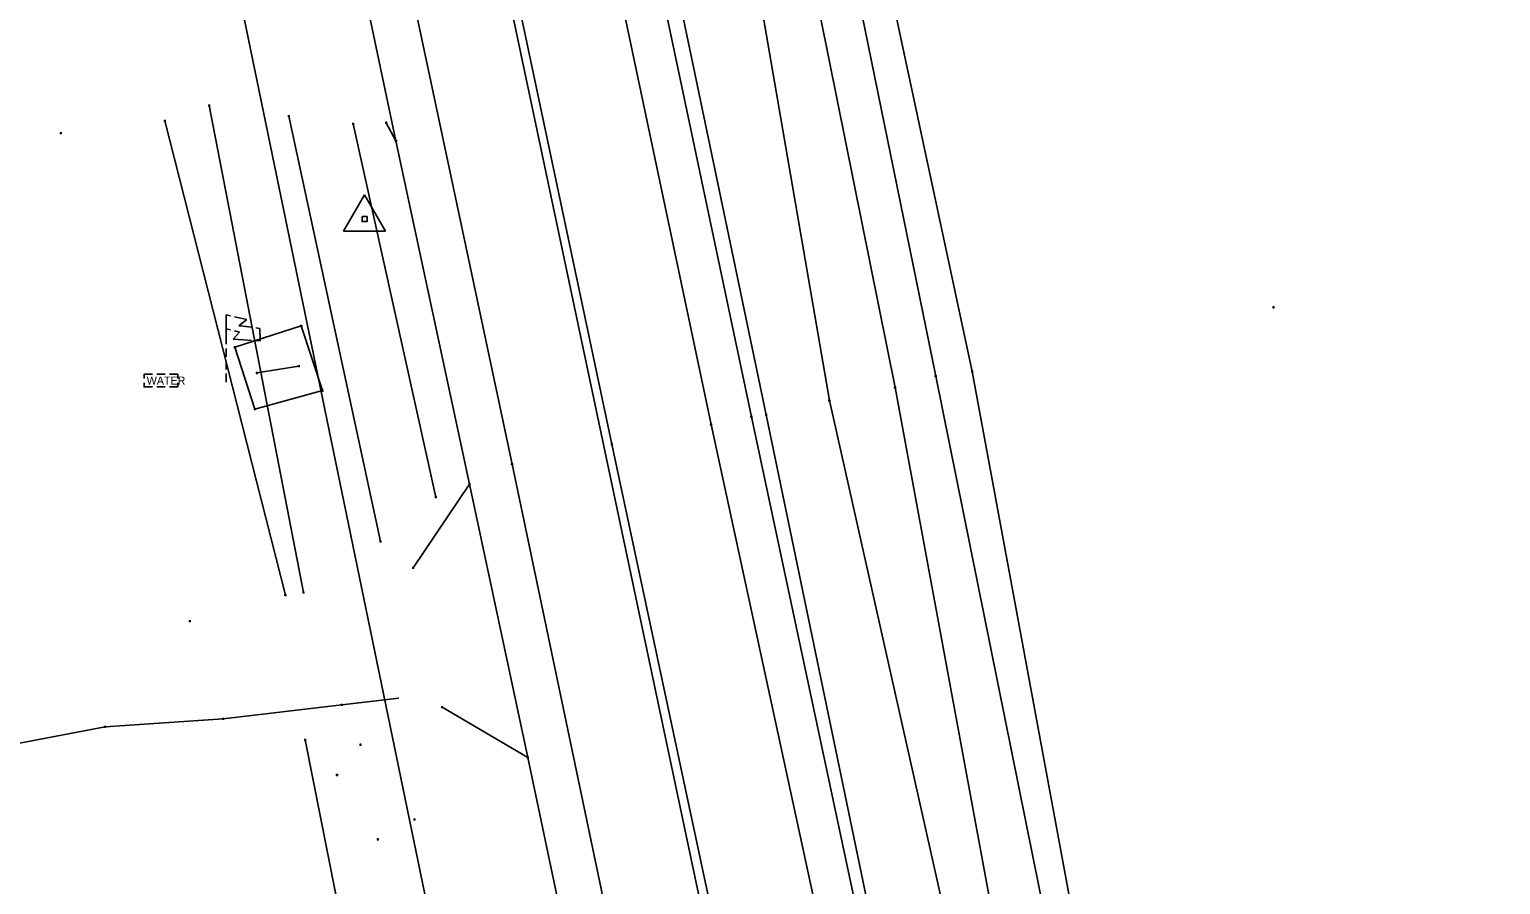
# Model space of a CAD drawing. Extents: x 1954856 to 2011933, y 399149 to 426294.
# Drawn here: x 2005094 to 2005268.6, y 407143.8 to 407245.4 of the extents above; entities that cross this region are included whole.
import ezdxf

# ---------------------------------------------------------------- set-up
doc = ezdxf.new("R2010")
doc.units = 0
for name, color, linetype in [('BankMent_ep', 7, 'Continuous'), ('BaselineSurvey', 7, 'Continuous'), ('Driveway_ep', 7, 'Continuous'), ('ElecAer_ep', 7, 'Continuous'), ('FlagPole_ep', 7, 'Continuous'), ('MeterWater_ep', 7, 'Continuous'), ('MonumentNL_ep', 7, 'Continuous'), ('PavtAsphalt_ep', 7, 'Continuous'), ('PavtAsphaltCrown_ep', 7, 'Continuous'), ('PointLocator_ep', 7, 'Continuous'), ('ShldrPaved_ep', 7, 'Continuous'), ('SignMulti_ep', 7, 'Continuous'), ('Stairs_ep', 7, 'Continuous'), ('TreeLineScatter_ep', 7, 'Continuous'), ('TreeLineWoods_ep', 7, 'Continuous')]:
    doc.layers.add(name, color=color, linetype=linetype)

msp = doc.modelspace()

# ---------------------------------------------------------------- linework, layer by layer
at = {"layer": 'BankMent_ep'}
for p, q in [((2005188.94, 407201.28), (2005172.13, 407299.28)), ((2005181.44, 407199.58), (2005161.06, 407297.29)), ((2005210.69, 407104.54), (2005188.94, 407201.28)), ((2005201.66, 407102.26), (2005181.44, 407199.58))]:
    msp.add_line(p, q, dxfattribs=at)
for points in [[(2005309.48, 406680.52), (2005302.97, 406714.33), (2005282.4, 406812.5), (2005263.07, 406909.67), (2005243.71, 407009.06), (2005221.27, 407106.71), (2005201.57, 407204.18), (2005181.73, 407301.56), (2005166.33, 407354.92)], [(2005306.06, 406678.23), (2005296.37, 406713.29), (2005277.07, 406810.93), (2005257.22, 406908.7), (2005233.22, 407007.14), (2005214.71, 407105.45), (2005196.74, 407202.84), (2005177.09, 407300.49), (2005163.81, 407354.47)], [(2005126.52, 407178.47), (2005115.31, 407236.34)], [(2005124.79, 407235.09), (2005135.67, 407184.52)], [(2005142.24, 407189.81), (2005132.4, 407234.16)]]:
    msp.add_lwpolyline(points, dxfattribs=at)
at = {"layer": 'BaselineSurvey'}
msp.add_line((2006223.92, 402174.38), (2005094.48, 407516.05), dxfattribs=at)
msp.add_line((2006223.92, 402174.38), (2005094.48, 407516.05), dxfattribs=at)
at = {"layer": 'Driveway_ep'}
for p, q in [((2005137.49, 407232.14), (2005136.34, 407234.3)), ((2005139.53, 407181.42), (2005146.22, 407191.34)), ((2005131.07, 407165.14), (2005116.97, 407163.47)), ((2005137.85, 407165.94), (2005131.07, 407165.14)), ((2005153.13, 407158.87), (2005142.98, 407164.86)), ((2005116.97, 407163.47), (2005102.98, 407162.51)), ((2005102.98, 407162.51), (2005083.54, 407158.8))]:
    msp.add_line(p, q, dxfattribs=at)
at = {"layer": 'ElecAer_ep'}
msp.add_lwpolyline([(2005261.7, 406565.27), (2005211.77, 406805.22), (2005164.45, 407028.42), (2005110.12, 407292.01), (2005075.05, 407240.4), (2005033.12, 407175.89)], dxfattribs=at)
at = {"layer": 'FlagPole_ep'}
for p, q in [((2005117.34, 407211.48), (2005117.84, 407211.36)), ((2005117.34, 407209.82), (2005117.34, 407211.48)), ((2005117.34, 407207.98), (2005117.34, 407209.82)), ((2005117.84, 407209.69), (2005117.34, 407209.82)), ((2005118.34, 407211.24), (2005119.79, 407210.91)), ((2005119.79, 407210.91), (2005118.83, 407210.17)), ((2005118.83, 407210.17), (2005119.34, 407210.11)), ((2005119.34, 407210.11), (2005120.34, 407209.99)), ((2005120.84, 407209.92), (2005121.34, 407209.86)), ((2005121.34, 407209.86), (2005121.37, 407208.37)), ((2005118.17, 407208.56), (2005118.92, 407209.41)), ((2005119.34, 407208.49), (2005118.17, 407208.56)), ((2005118.92, 407209.41), (2005118.34, 407209.56)), ((2005120.34, 407208.43), (2005119.34, 407208.49)), ((2005121.37, 407208.37), (2005120.84, 407208.4)), ((2005117.34, 407206.48), (2005117.34, 407207.48)), ((2005117.34, 407204.98), (2005117.34, 407205.98)), ((2005117.34, 407203.48), (2005117.34, 407204.48)), ((2005117.34, 407203.48), (2005117.34, 407203.48))]:
    msp.add_line(p, q, dxfattribs=at)
at = {"layer": 'MeterWater_ep'}
msp.add_line((2005109.59, 407203.65), (2005109.59, 407203.65), dxfattribs=at)
for points in [[(2005107.59, 407203.9), (2005107.59, 407204.4), (2005108.59, 407204.4)], [(2005108.59, 407202.9), (2005107.59, 407202.9), (2005107.59, 407203.4)], [(2005109.09, 407204.4), (2005110.09, 407204.4)], [(2005110.09, 407202.9), (2005109.09, 407202.9)], [(2005110.59, 407204.4), (2005111.59, 407204.4), (2005111.59, 407203.9)], [(2005111.59, 407203.4), (2005111.59, 407202.9), (2005110.59, 407202.9)]]:
    msp.add_lwpolyline(points, dxfattribs=at)
at = {"layer": 'MonumentNL_ep'}
for p, q in [((2005131.26, 407221.4), (2005133.76, 407225.73)), ((2005133.76, 407225.73), (2005136.26, 407221.4)), ((2005133.76, 407222.84), (2005133.76, 407222.84)), ((2005131.26, 407221.4), (2005136.26, 407221.4))]:
    msp.add_line(p, q, dxfattribs=at)
msp.add_lwpolyline([(2005133.46, 407223.14), (2005134.06, 407223.14), (2005134.06, 407222.54), (2005133.46, 407222.54)], close=True, dxfattribs=at)
at = {"layer": 'PavtAsphalt_ep'}
for p, q in [((2005174.9, 407198.44), (2005154.4, 407295.58)), ((2005151.27, 407193.74), (2005130.48, 407291.72)), ((2005195.99, 407101.08), (2005174.9, 407198.44)), ((2005171.88, 407095.33), (2005151.27, 407193.74))]:
    msp.add_line(p, q, dxfattribs=at)
at = {"layer": 'PavtAsphaltCrown_ep'}
for p, q in [((2005163.1, 407196.11), (2005142.45, 407294.03)), ((2005183.98, 407098.33), (2005163.1, 407196.11))]:
    msp.add_line(p, q, dxfattribs=at)
at = {"layer": 'PointLocator_ep'}
for p, q in [((2005115.44, 407236.34), (2005115.19, 407236.34)), ((2005115.31, 407236.22), (2005115.31, 407236.47)), ((2005115.31, 407236.34), (2005115.31, 407236.34)), ((2005110.18, 407234.52), (2005109.93, 407234.52)), ((2005110.06, 407234.4), (2005110.06, 407234.65)), ((2005110.06, 407234.52), (2005110.06, 407234.52)), ((2005124.91, 407235.09), (2005124.66, 407235.09)), ((2005124.79, 407234.96), (2005124.79, 407235.21)), ((2005124.79, 407235.09), (2005124.79, 407235.09)), ((2005132.4, 407234.04), (2005132.4, 407234.29)), ((2005136.46, 407234.3), (2005136.21, 407234.3)), ((2005136.34, 407234.18), (2005136.34, 407234.43)), ((2005136.34, 407234.3), (2005136.34, 407234.3)), ((2005097.82, 407233.06), (2005097.57, 407233.06)), ((2005097.69, 407232.93), (2005097.69, 407233.18)), ((2005097.69, 407233.06), (2005097.69, 407233.06)), ((2005132.53, 407234.16), (2005132.28, 407234.16)), ((2005132.4, 407234.16), (2005132.4, 407234.16)), ((2005137.62, 407232.14), (2005137.37, 407232.14)), ((2005137.49, 407232.01), (2005137.49, 407232.26)), ((2005137.49, 407232.14), (2005137.49, 407232.14)), ((2005241.8, 407212.36), (2005241.55, 407212.36)), ((2005241.68, 407212.23), (2005241.68, 407212.48)), ((2005241.68, 407212.36), (2005241.68, 407212.36)), ((2005126.38, 407210.16), (2005126.13, 407210.16)), ((2005126.25, 407210.03), (2005126.25, 407210.28)), ((2005126.25, 407210.16), (2005126.25, 407210.16)), ((2005118.5, 407207.61), (2005118.25, 407207.61)), ((2005118.37, 407207.49), (2005118.37, 407207.74)), ((2005118.37, 407207.61), (2005118.37, 407207.61)), ((2005121.09, 407204.56), (2005120.84, 407204.56)), ((2005120.96, 407204.43), (2005120.96, 407204.68)), ((2005120.96, 407204.56), (2005120.96, 407204.56)), ((2005126.07, 407205.37), (2005125.82, 407205.37)), ((2005125.95, 407205.25), (2005125.95, 407205.5)), ((2005125.95, 407205.37), (2005125.95, 407205.37)), ((2005206.02, 407204.74), (2005205.77, 407204.74)), ((2005205.9, 407204.61), (2005205.9, 407204.86)), ((2005205.9, 407204.74), (2005205.9, 407204.74)), ((2005196.86, 407202.84), (2005196.61, 407202.84)), ((2005196.74, 407202.71), (2005196.74, 407202.96)), ((2005196.74, 407202.84), (2005196.74, 407202.84)), ((2005201.69, 407204.18), (2005201.44, 407204.18)), ((2005201.57, 407204.06), (2005201.57, 407204.31)), ((2005201.57, 407204.18), (2005201.57, 407204.18)), ((2005128.88, 407202.46), (2005128.63, 407202.46)), ((2005128.76, 407202.33), (2005128.76, 407202.58)), ((2005128.76, 407202.46), (2005128.76, 407202.46)), ((2005189.06, 407201.28), (2005188.81, 407201.28)), ((2005188.94, 407201.15), (2005188.94, 407201.4)), ((2005188.94, 407201.28), (2005188.94, 407201.28)), ((2005120.87, 407200.26), (2005120.62, 407200.26)), ((2005120.74, 407200.14), (2005120.74, 407200.39)), ((2005120.74, 407200.26), (2005120.74, 407200.26)), ((2005179.81, 407199.37), (2005179.56, 407199.37)), ((2005179.68, 407199.25), (2005179.68, 407199.5)), ((2005179.68, 407199.37), (2005179.68, 407199.37)), ((2005181.57, 407199.58), (2005181.32, 407199.58)), ((2005181.44, 407199.45), (2005181.44, 407199.7)), ((2005181.44, 407199.58), (2005181.44, 407199.58)), ((2005175.02, 407198.44), (2005174.77, 407198.44)), ((2005174.9, 407198.31), (2005174.9, 407198.56)), ((2005174.9, 407198.44), (2005174.9, 407198.44)), ((2005163.23, 407196.11), (2005162.98, 407196.11)), ((2005163.1, 407195.99), (2005163.1, 407196.24)), ((2005163.1, 407196.11), (2005163.1, 407196.11)), ((2005151.39, 407193.74), (2005151.14, 407193.74)), ((2005151.27, 407193.61), (2005151.27, 407193.86)), ((2005151.27, 407193.74), (2005151.27, 407193.74)), ((2005146.35, 407191.34), (2005146.1, 407191.34)), ((2005146.22, 407191.22), (2005146.22, 407191.47)), ((2005146.22, 407191.34), (2005146.22, 407191.34)), ((2005142.36, 407189.81), (2005142.11, 407189.81)), ((2005142.24, 407189.69), (2005142.24, 407189.94)), ((2005142.24, 407189.81), (2005142.24, 407189.81)), ((2005135.79, 407184.52), (2005135.54, 407184.52)), ((2005135.67, 407184.4), (2005135.67, 407184.65)), ((2005135.67, 407184.52), (2005135.67, 407184.52)), ((2005139.66, 407181.42), (2005139.41, 407181.42)), ((2005139.53, 407181.29), (2005139.53, 407181.54)), ((2005139.53, 407181.42), (2005139.53, 407181.42)), ((2005124.36, 407178.06), (2005124.36, 407178.31)), ((2005126.64, 407178.47), (2005126.39, 407178.47)), ((2005126.52, 407178.35), (2005126.52, 407178.6)), ((2005126.52, 407178.47), (2005126.52, 407178.47)), ((2005124.48, 407178.18), (2005124.23, 407178.18)), ((2005124.36, 407178.18), (2005124.36, 407178.18)), ((2005113.15, 407175.07), (2005112.9, 407175.07)), ((2005113.03, 407174.94), (2005113.03, 407175.19)), ((2005113.03, 407175.07), (2005113.03, 407175.07)), ((2005131.2, 407165.14), (2005130.95, 407165.14)), ((2005131.07, 407165.02), (2005131.07, 407165.27)), ((2005131.07, 407165.14), (2005131.07, 407165.14)), ((2005143.1, 407164.86), (2005142.85, 407164.86)), ((2005142.98, 407164.74), (2005142.98, 407164.99)), ((2005142.98, 407164.86), (2005142.98, 407164.86)), ((2005102.98, 407162.39), (2005102.98, 407162.64)), ((2005117.09, 407163.47), (2005116.84, 407163.47)), ((2005116.97, 407163.34), (2005116.97, 407163.59)), ((2005116.97, 407163.47), (2005116.97, 407163.47)), ((2005103.1, 407162.51), (2005102.85, 407162.51)), ((2005102.98, 407162.51), (2005102.98, 407162.51)), ((2005126.84, 407160.96), (2005126.59, 407160.96)), ((2005126.72, 407160.83), (2005126.72, 407161.08)), ((2005126.72, 407160.96), (2005126.72, 407160.96)), ((2005133.41, 407160.4), (2005133.16, 407160.4)), ((2005133.29, 407160.27), (2005133.29, 407160.52)), ((2005133.29, 407160.4), (2005133.29, 407160.4)), ((2005153.26, 407158.87), (2005153.01, 407158.87)), ((2005153.13, 407158.74), (2005153.13, 407158.99)), ((2005153.13, 407158.87), (2005153.13, 407158.87)), ((2005130.62, 407156.8), (2005130.37, 407156.8)), ((2005130.49, 407156.67), (2005130.49, 407156.92)), ((2005130.49, 407156.8), (2005130.49, 407156.8)), ((2005139.81, 407151.52), (2005139.56, 407151.52)), ((2005139.69, 407151.39), (2005139.69, 407151.64)), ((2005139.69, 407151.52), (2005139.69, 407151.52)), ((2005135.45, 407149.15), (2005135.2, 407149.15)), ((2005135.33, 407149.03), (2005135.33, 407149.28)), ((2005135.33, 407149.15), (2005135.33, 407149.15))]:
    msp.add_line(p, q, dxfattribs=at)
at = {"layer": 'ShldrPaved_ep'}
for p, q in [((2005179.68, 407199.37), (2005159.17, 407296.71)), ((2005137.49, 407232.14), (2005130.38, 407265.93)), ((2005146.22, 407191.34), (2005137.49, 407232.14)), ((2005200.41, 407102.08), (2005179.68, 407199.37)), ((2005153.13, 407158.87), (2005146.22, 407191.34)), ((2005166.79, 407094.24), (2005153.13, 407158.87))]:
    msp.add_line(p, q, dxfattribs=at)
at = {"layer": 'SignMulti_ep'}
msp.add_lwpolyline([(2005120.96, 407204.56), (2005125.95, 407205.37)], dxfattribs=at)
at = {"layer": 'Stairs_ep'}
msp.add_lwpolyline([(2005128.76, 407202.46), (2005120.74, 407200.26), (2005118.37, 407207.61), (2005126.25, 407210.16)], close=True, dxfattribs=at)
at = {"layer": 'TreeLineScatter_ep'}
msp.add_lwpolyline([(2005110.06, 407234.52), (2005124.36, 407178.18)], dxfattribs=at)
at = {"layer": 'TreeLineWoods_ep'}
for points in [[(2005396.16, 406442.29), (2005348.96, 406489.45), (2005344.65, 406519.64), (2005321.38, 406616.19), (2005301.57, 406714.44), (2005284.12, 406812.99), (2005265.54, 406910.08), (2005242.13, 407008.24), (2005223.9, 407107.37), (2005205.9, 407204.74), (2005185.1, 407302.14), (2005170.72, 407356.46), (2005205.33, 407355.25)], [(2005114.03, 406671.84), (2005228.71, 406714.83), (2005204.69, 406796.01), (2005184, 406894.69), (2005163.82, 406990.27), (2005141.12, 407088.27), (2005126.72, 407160.96)]]:
    msp.add_lwpolyline(points, dxfattribs=at)

# ---------------------------------------------------------------- texts
at = {"layer": 'MeterWater_ep'}
msp.add_text('WATER', height=0.95, dxfattribs=at).set_placement((2005107.9, 407203.18))

doc.saveas('drawing.dxf')
